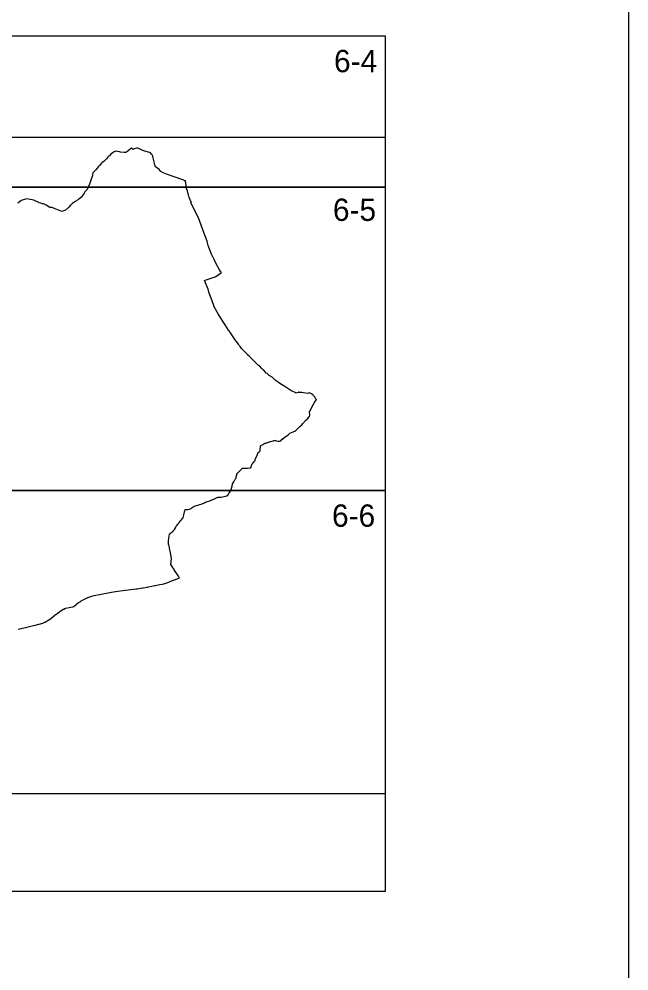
# Model space of a CAD drawing. Extents: x -449577 to -436680, y -1132317 to -1125726.
# Drawn here: x -439194.4 to -438943.1, y -1131954.1 to -1131561.7 of the extents above; entities that cross this region are included whole.
import ezdxf

# ---------------------------------------------------------------- set-up
doc = ezdxf.new("R2010")
doc.units = 0
for name, color, linetype in [('Vrstva 1', 7, 'Continuous'), ('Vrstva 10', 7, 'Continuous'), ('Vrstva 4', 7, 'Continuous')]:
    doc.layers.add(name, color=color, linetype=linetype)

msp = doc.modelspace()

# ---------------------------------------------------------------- linework, layer by layer
at = {"layer": 'Vrstva 1'}
msp.add_lwpolyline([(-440428.09, -1131267.17), (-440428.09, -1132317.17), (-438943.09, -1132317.17), (-438943.09, -1131267.17)], close=True, dxfattribs=at)
msp.add_lwpolyline([(-439194.8, -1131813.29), (-439191.26, -1131812.42), (-439188.49, -1131811.75), (-439187.82, -1131811.54), (-439186.33, -1131811.18), (-439186.12, -1131811.12), (-439184.69, -1131810.73), (-439184.09, -1131810.47), (-439183.87, -1131810.37), (-439183.71, -1131810.31), (-439182.89, -1131809.86), (-439182.83, -1131809.82), (-439181.52, -1131809.04), (-439180.37, -1131807.99), (-439179.72, -1131807.49), (-439179.59, -1131807.38), (-439179.57, -1131807.37), (-439179.41, -1131807.24), (-439179.26, -1131807.14), (-439178.46, -1131806.58), (-439178.4, -1131806.54), (-439178.33, -1131806.49), (-439177.82, -1131806.14), (-439177.45, -1131805.88), (-439176.79, -1131805.42), (-439176.2, -1131805.01), (-439176.04, -1131805.04), (-439176.03, -1131805.04), (-439176.01, -1131805.02), (-439175.28, -1131804.63), (-439172.32, -1131804.05), (-439171.9, -1131803.9), (-439169.87, -1131802.27), (-439169.4, -1131801.93), (-439169.37, -1131801.91), (-439169.01, -1131801.65), (-439168.83, -1131801.53), (-439167.44, -1131800.83), (-439166.03, -1131800.19), (-439165.73, -1131800.04), (-439164.47, -1131799.58), (-439163.47, -1131799.33), (-439157.76, -1131798.27), (-439156.34, -1131798.01), (-439154.63, -1131797.76), (-439150.76, -1131797.19), (-439150.52, -1131797.16), (-439146.22, -1131796.64), (-439145.69, -1131796.58), (-439143.54, -1131796.22), (-439143.22, -1131796.17), (-439141.56, -1131795.9), (-439141.16, -1131795.83), (-439139.75, -1131795.54), (-439138.46, -1131795.27), (-439138.25, -1131795.23), (-439137.08, -1131795), (-439136.41, -1131794.87), (-439136.39, -1131794.87), (-439135.48, -1131794.66), (-439135.41, -1131794.64), (-439134.76, -1131794.48), (-439134.41, -1131794.37), (-439133.52, -1131794.08), (-439133.08, -1131793.93), (-439132.43, -1131793.69), (-439132.31, -1131793.65), (-439131.22, -1131793.16), (-439131.22, -1131793.16), (-439131.1, -1131793.12), (-439130.45, -1131792.89), (-439130.36, -1131792.86), (-439129.93, -1131792.7), (-439128.27, -1131792.12), (-439128.29, -1131792.07), (-439128.4, -1131791.9), (-439128.56, -1131791.67), (-439128.78, -1131791.35), (-439130.48, -1131788.71), (-439130.69, -1131788.36), (-439130.86, -1131788.09), (-439131.3, -1131787.38), (-439131.83, -1131786.53), (-439131.67, -1131784.17), (-439131.66, -1131784.08), (-439132.05, -1131781.78), (-439132.05, -1131781.76), (-439132.06, -1131781.74), (-439132.06, -1131781.74), (-439132.06, -1131781.71), (-439132.47, -1131779.88), (-439132.48, -1131779.69), (-439132.54, -1131778.89), (-439132.64, -1131778.61), (-439132.65, -1131778.59), (-439132.76, -1131778.37), (-439132.8, -1131778.29), (-439132.81, -1131777.91), (-439132.84, -1131777.21), (-439132.79, -1131776.72), (-439132.79, -1131776.7), (-439132.7, -1131775.84), (-439132.68, -1131775.73), (-439132.39, -1131774.09), (-439132.31, -1131774.01), (-439132.01, -1131773.67), (-439131.95, -1131773.6), (-439131.69, -1131773.48), (-439131.63, -1131773.42), (-439131.37, -1131773.22), (-439131.14, -1131773.04), (-439130.93, -1131772.88), (-439130.87, -1131772.84), (-439130.79, -1131772.71), (-439130.71, -1131772.59), (-439130.6, -1131772.42), (-439130.38, -1131772.09), (-439129.96, -1131771.44), (-439129.83, -1131771.19), (-439129.82, -1131771.18), (-439129.68, -1131770.89), (-439129.63, -1131770.8), (-439129.45, -1131770.47), (-439129.31, -1131770.32), (-439129.01, -1131770.01), (-439128.84, -1131769.83), (-439128.56, -1131769.48), (-439128.43, -1131769.31), (-439127.74, -1131768.46), (-439127.08, -1131767.65), (-439126.79, -1131767.29), (-439126.55, -1131766.12), (-439126.49, -1131765.89), (-439126.42, -1131765.61), (-439126.1, -1131764.3), (-439126.02, -1131764.02), (-439126.02, -1131763.99), (-439126, -1131763.94), (-439125.84, -1131763.93), (-439125.82, -1131763.93), (-439125.58, -1131763.93), (-439124.89, -1131763.91), (-439124.88, -1131763.91), (-439124.85, -1131763.91), (-439124.17, -1131763.73), (-439123.97, -1131763.67), (-439123.55, -1131763.56), (-439123.53, -1131763.55), (-439123.47, -1131763.49), (-439123.17, -1131763.21), (-439123.05, -1131763.13), (-439122.71, -1131762.87), (-439122.29, -1131762.55), (-439122.22, -1131762.53), (-439121.66, -1131762.37), (-439118.96, -1131761.61), (-439118.37, -1131761.34), (-439118.04, -1131761.18), (-439117.99, -1131761.16), (-439117.89, -1131761.11), (-439117.53, -1131760.93), (-439117.48, -1131760.91), (-439117.45, -1131760.89), (-439117.44, -1131760.89), (-439117.41, -1131760.87), (-439117.1, -1131760.72), (-439117.04, -1131760.68), (-439116.93, -1131760.63), (-439115.85, -1131760.3), (-439115.42, -1131760.12), (-439114.9, -1131759.9), (-439113.89, -1131759.49), (-439112.47, -1131758.86), (-439112.33, -1131758.85), (-439111.2, -1131758.8), (-439108.8, -1131758.24), (-439108.27, -1131757.84), (-439108.2, -1131757.72), (-439108.11, -1131757.54), (-439107.85, -1131757.03), (-439107.5, -1131756.6), (-439107.48, -1131756.57), (-439107.27, -1131756.28), (-439107.16, -1131756.12), (-439107.15, -1131756.11), (-439106.61, -1131754.33), (-439106.6, -1131754.3), (-439106.4, -1131753.35), (-439106.14, -1131752.89), (-439105.95, -1131752.56), (-439105.4, -1131751.44), (-439105.02, -1131750.93), (-439104.99, -1131750.8), (-439104.92, -1131750.5), (-439104.89, -1131750.36), (-439104.83, -1131750.11), (-439104.81, -1131750.01), (-439104.49, -1131749), (-439104.48, -1131748.99), (-439104.19, -1131748.71), (-439103.53, -1131748.08), (-439103.48, -1131748.03), (-439103.01, -1131747.55), (-439102.75, -1131747.29), (-439102.65, -1131747.18), (-439102.28, -1131746.86), (-439102.24, -1131746.86), (-439102.23, -1131746.86), (-439101.82, -1131746.85), (-439101.65, -1131746.86), (-439101.02, -1131746.88), (-439100.31, -1131746.88), (-439099.34, -1131746.79), (-439099.31, -1131746.79), (-439099.06, -1131746.76), (-439098.84, -1131746.4), (-439098.79, -1131746.27), (-439098.77, -1131746.22), (-439098.75, -1131746.16), (-439098.39, -1131745.14), (-439098.25, -1131744.97), (-439098.15, -1131744.86), (-439098.11, -1131744.82), (-439098.05, -1131744.74), (-439097.93, -1131744.61), (-439097.66, -1131744.29), (-439097.57, -1131744.19), (-439097.47, -1131744.07), (-439097.13, -1131743.68), (-439097.06, -1131743.29), (-439097, -1131742.98), (-439096.93, -1131742.85), (-439096.38, -1131741.93), (-439096.27, -1131741.54), (-439096.08, -1131740.84), (-439095.96, -1131740.55), (-439095.67, -1131740.28), (-439095.12, -1131739.77), (-439095.05, -1131739.71), (-439094.95, -1131737.6), (-439093.93, -1131737.11), (-439093.53, -1131736.9), (-439093.28, -1131736.77), (-439092.99, -1131736.61), (-439092.77, -1131736.53), (-439092.43, -1131736.4), (-439092.38, -1131736.39), (-439091.29, -1131735.98), (-439091.28, -1131735.98), (-439090.79, -1131735.92), (-439090.71, -1131735.9), (-439089.68, -1131735.64), (-439089.53, -1131735.6), (-439089.44, -1131735.57), (-439089.27, -1131735.52), (-439088.74, -1131735.35), (-439088.74, -1131735.35), (-439088.73, -1131735.36), (-439088.73, -1131735.36), (-439088.7, -1131735.42), (-439088.57, -1131735.64), (-439087.69, -1131735.74), (-439087.49, -1131735.76), (-439087.13, -1131735.8), (-439087.04, -1131735.76), (-439086.61, -1131735.58), (-439085.96, -1131734.87), (-439084.32, -1131733.71), (-439084.23, -1131733.64), (-439084.06, -1131733.53), (-439083.55, -1131733.11), (-439082.8, -1131732.51), (-439081.53, -1131731.94), (-439080.91, -1131731.67), (-439080.37, -1131731.43), (-439080.31, -1131731.4), (-439078.66, -1131729.73), (-439077.82, -1131728.84), (-439077.46, -1131728.46), (-439076.27, -1131727.1), (-439075.67, -1131726.64), (-439075.62, -1131726.6), (-439074.78, -1131725.59), (-439074.58, -1131725.02), (-439074.67, -1131723.69), (-439074.45, -1131723.2), (-439073.81, -1131721.75), (-439072.35, -1131719.27), (-439072.32, -1131719.22), (-439072.32, -1131719.22), (-439072.3, -1131719.19), (-439072.27, -1131719.15), (-439072.12, -1131718.96), (-439071.86, -1131718.62), (-439072.12, -1131718.32), (-439072.26, -1131718.1), (-439072.73, -1131717.36), (-439072.93, -1131717.17), (-439073.08, -1131717.01), (-439073.27, -1131716.81), (-439073.85, -1131716.24), (-439074.7, -1131715.77), (-439075.15, -1131715.95), (-439075.48, -1131716.07), (-439077.23, -1131715.8), (-439077.84, -1131715.71), (-439077.98, -1131715.7), (-439078.57, -1131715.68), (-439078.95, -1131715.63), (-439079.11, -1131715.6), (-439079.15, -1131715.6), (-439079.18, -1131715.59), (-439079.18, -1131715.59), (-439079.21, -1131715.6), (-439079.31, -1131715.63), (-439079.44, -1131715.66), (-439080.34, -1131715.9), (-439080.41, -1131715.87), (-439082.48, -1131714.83), (-439084.5, -1131713.55), (-439087.41, -1131711.73), (-439087.57, -1131711.59), (-439087.61, -1131711.56), (-439087.7, -1131711.48), (-439088.84, -1131710.55), (-439089.99, -1131709.5), (-439090.1, -1131709.4), (-439091.31, -1131708.64), (-439091.59, -1131708.41), (-439092.22, -1131707.91), (-439092.53, -1131707.67), (-439093.03, -1131707.14), (-439093.75, -1131706.38), (-439093.9, -1131706.22), (-439094.36, -1131705.73), (-439095.33, -1131704.7), (-439095.53, -1131704.59), (-439095.53, -1131704.59), (-439095.71, -1131704.5), (-439095.91, -1131704.4), (-439096.74, -1131703.57), (-439097.37, -1131702.94), (-439098.55, -1131701.77), (-439099.48, -1131700.83), (-439099.64, -1131700.68), (-439100.08, -1131700.23), (-439100.32, -1131699.99), (-439100.41, -1131699.9), (-439100.45, -1131699.86), (-439100.97, -1131699.34), (-439101.61, -1131698.69), (-439101.69, -1131698.61), (-439101.71, -1131698.59), (-439101.86, -1131698.44), (-439102.69, -1131697.6), (-439103.07, -1131697.1), (-439103.35, -1131696.73), (-439103.67, -1131696.3), (-439104.03, -1131695.82), (-439104.98, -1131694.56), (-439105.35, -1131694.02), (-439107.89, -1131690.28), (-439108.06, -1131690.02), (-439108.83, -1131688.83), (-439109.5, -1131687.82), (-439110.34, -1131686.49), (-439111.14, -1131685.22), (-439111.22, -1131685.09), (-439112.31, -1131683.24), (-439113.99, -1131680.39), (-439113.99, -1131680.38), (-439113.99, -1131680.38), (-439114, -1131680.38), (-439114.33, -1131679.4), (-439114.78, -1131678.1), (-439114.84, -1131677.9), (-439116.22, -1131674.39), (-439116.51, -1131673.14), (-439117.99, -1131669.46), (-439117.36, -1131669.26), (-439113.64, -1131668.02), (-439111.67, -1131666.8), (-439111.49, -1131666.69), (-439111.43, -1131666.65), (-439111.23, -1131666.53), (-439110.96, -1131666.36), (-439111.88, -1131665.17), (-439113.29, -1131662.39), (-439114.04, -1131660.92), (-439114.57, -1131659.76), (-439114.59, -1131659.72), (-439114.65, -1131659.59), (-439114.66, -1131659.56), (-439114.68, -1131659.53), (-439114.72, -1131659.44), (-439115.05, -1131658.71), (-439115.37, -1131657.92), (-439116.08, -1131656.15), (-439116.49, -1131655.11), (-439116.64, -1131654.48), (-439116.9, -1131653.35), (-439117.64, -1131651.46), (-439117.84, -1131650.86), (-439118.78, -1131648.23), (-439119.05, -1131647.51), (-439120.24, -1131644.42), (-439120.31, -1131644.24), (-439120.34, -1131644.16), (-439123.69, -1131637.35), (-439123.38, -1131637.21), (-439123.36, -1131637.2), (-439123.46, -1131637.03), (-439123.54, -1131636.93), (-439123.71, -1131636.7), (-439123.77, -1131636.62), (-439124.38, -1131635.14), (-439124.43, -1131634.85), (-439124.53, -1131634.39), (-439124.54, -1131634.33), (-439125.05, -1131632.49), (-439125.35, -1131631.86), (-439125.36, -1131631.78), (-439125.4, -1131631.42), (-439125.54, -1131630.33), (-439125.82, -1131628.49), (-439125.88, -1131628.47), (-439126.18, -1131628.37), (-439126.56, -1131628.11), (-439126.57, -1131628.11), (-439130.87, -1131626.7), (-439133.66, -1131625.72), (-439134.97, -1131625.1), (-439135.94, -1131624.54), (-439136.66, -1131623.76), (-439138.34, -1131622.49), (-439138.4, -1131622.19), (-439138.98, -1131619.49), (-439139.13, -1131618.95), (-439139.31, -1131618.44), (-439139.36, -1131618.28), (-439139.61, -1131617.76), (-439139.86, -1131617.45), (-439140.44, -1131616.76), (-439141.19, -1131616.55), (-439143.37, -1131615.89), (-439145.46, -1131614.93), (-439146.08, -1131614.93), (-439147.03, -1131615.3), (-439147.16, -1131615.39), (-439147.23, -1131615.44), (-439147.37, -1131615.54), (-439147.41, -1131615.57), (-439147.43, -1131615.55), (-439147.64, -1131615.3), (-439147.89, -1131615.02), (-439147.97, -1131614.92), (-439148.06, -1131614.96), (-439148.57, -1131615.35), (-439148.76, -1131615.5), (-439149.43, -1131616.02), (-439150.18, -1131616.58), (-439150.52, -1131616.8), (-439151.11, -1131616.76), (-439152.59, -1131616.61), (-439153.05, -1131616.52), (-439154.64, -1131616.2), (-439154.94, -1131616.31), (-439155.5, -1131616.66), (-439156.05, -1131616.98), (-439156.54, -1131617.44), (-439157.07, -1131617.93), (-439157.47, -1131618.32), (-439157.48, -1131618.33), (-439157.81, -1131618.67), (-439157.94, -1131618.81), (-439158.45, -1131619.36), (-439158.9, -1131619.91), (-439159.06, -1131620.1), (-439159.42, -1131620.53), (-439160.16, -1131620.86), (-439160.18, -1131620.86), (-439160.38, -1131621.11), (-439161.24, -1131622.13), (-439161.62, -1131622.58), (-439162.75, -1131623.94), (-439162.76, -1131623.95), (-439164, -1131625.12), (-439164.12, -1131625.96), (-439164.17, -1131626.33), (-439164.21, -1131626.43), (-439164.69, -1131627.78), (-439165.13, -1131629.02), (-439165.16, -1131629.1), (-439165.46, -1131629.79), (-439166.39, -1131631.97), (-439166.41, -1131631.98), (-439166.98, -1131632.66), (-439167.28, -1131633.01), (-439167.28, -1131633.02), (-439167.62, -1131633.56), (-439168.49, -1131634.95), (-439168.58, -1131635.09), (-439168.75, -1131635.22), (-439169.28, -1131635.61), (-439169.89, -1131636.06), (-439169.89, -1131636.06), (-439170.86, -1131636.69), (-439170.99, -1131636.78), (-439171.17, -1131636.9), (-439172.47, -1131637.76), (-439172.48, -1131637.77), (-439172.74, -1131638.03), (-439172.86, -1131638.15), (-439173.08, -1131638.38), (-439173.36, -1131638.66), (-439173.93, -1131639.23), (-439175.09, -1131640.39), (-439175.29, -1131640.47), (-439176.79, -1131641.04), (-439179.6, -1131639.92), (-439179.6, -1131639.93), (-439179.61, -1131639.95), (-439180.52, -1131639.57), (-439180.83, -1131639.44), (-439180.85, -1131639.44), (-439181.24, -1131639.44), (-439181.72, -1131639.44), (-439183.28, -1131638.45), (-439183.54, -1131638.32), (-439183.83, -1131638.16), (-439183.89, -1131638.13), (-439183.93, -1131638.11), (-439184.47, -1131637.88), (-439184.52, -1131637.88), (-439184.53, -1131637.88), (-439184.68, -1131637.87), (-439184.8, -1131637.86), (-439185.11, -1131637.84), (-439185.13, -1131637.84), (-439185.13, -1131637.84), (-439185.24, -1131637.8), (-439185.48, -1131637.7), (-439186.08, -1131637.45), (-439186.24, -1131637.38), (-439187.76, -1131636.65), (-439188.38, -1131636.47), (-439189.05, -1131636.27), (-439191.37, -1131635.84), (-439191.38, -1131635.84), (-439191.78, -1131635.95), (-439193.52, -1131636.53), (-439193.65, -1131636.64), (-439194.86, -1131637.6)], dxfattribs=at)
at = {"layer": 'Vrstva 10'}
msp.add_lwpolyline([(-439043.5, -1131610.43), (-439043.5, -1131921.41), (-439376.37, -1131921.41), (-439376.37, -1131756.11), (-439356, -1131756.11), (-439356, -1131631.11), (-439356, -1131610.43), (-439043.5, -1131610.43)], dxfattribs=at)
at = {"layer": 'Vrstva 4'}
msp.add_line((-439356, -1131568.61), (-439043.5, -1131568.61), dxfattribs=at)
msp.add_lwpolyline([(-439043.5, -1131568.61), (-439043.5, -1131631.11), (-439199.75, -1131631.11), (-439199.75, -1131568.61)], dxfattribs=at)
for points in [[(-439043.5, -1131631.11), (-439043.5, -1131756.11), (-439199.75, -1131756.11), (-439199.75, -1131631.11)], [(-439043.5, -1131756.11), (-439043.5, -1131881.11), (-439199.75, -1131881.11), (-439199.75, -1131756.11)]]:
    msp.add_lwpolyline(points, close=True, dxfattribs=at)

# ---------------------------------------------------------------- texts
at = {"layer": 'Vrstva 1'}
for s, p in [('6-4', (-439064.63, -1131583.66)), ('6-5', (-439065.08, -1131644.95)), ('6-6', (-439065.45, -1131771.02))]:
    msp.add_text(s, height=9.2, dxfattribs=at).set_placement(p)

doc.saveas('drawing.dxf')
